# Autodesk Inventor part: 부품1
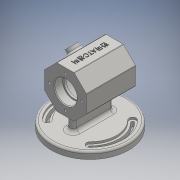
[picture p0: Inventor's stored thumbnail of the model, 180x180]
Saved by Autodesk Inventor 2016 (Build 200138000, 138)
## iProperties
Created: 2017-06
Part Number: 부품1
Material: 일반
Document SubType Name: Modeling
Designer: USER
Density: 1 g/cm^3
Appearance: 기본값
Author: USER
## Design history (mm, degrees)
sketch "스케치1"
  geometry: C1 r 55 at (0, 0); 1 further point
  constraints: 1 centre point, 1 coincident
  dimensions: "d0" = 110 diameter of C1
extrude "돌출1" new body sketch "스케치1" distance "d1" = 10; taper "d2" = 0 deg
sketch "스케치2"
  geometry: L1 (-55, 0)-(55, 0) reference; L2 (0, 62)-(0, 94.472); L3 (0, 62)-(-12.426, 92); L4 (0, 62)-(12.426, 92); L5 (12.426, 92)-(-12.426, 92); L6 (0, 62)-(-30, 74.426); L7 (0, 62)-(-30, 49.574); L8 (0, 62)-(-12.426, 32); L9 (0, 62)-(12.426, 32); L10 (0, 62)-(30, 49.574); L11 (0, 62)-(30, 74.426); L12 (-12.426, 92)-(-30, 74.426); L13 (-30, 49.574)-(-30, 74.426); L14 (-30, 49.574)-(-12.426, 32); L15 (-12.426, 32)-(12.426, 32); L16 (12.426, 32)-(30, 49.574); L17 (30, 49.574)-(30, 74.426); L18 (30, 74.426)-(12.426, 92); 3 further points
  constraints: 34 end point, 2 perpendicular, 2 vertical alignment, 1 coincident, 1 midpoint, 1 point on line, 1 vertical, 12 other
  dimensions: "d4" = 62 distance from line of point (0, 62) L1; "d10" = 22.5 deg angle of L2 L3; "d11" = 22.5 deg angle of L2 L4; "d12" = 92 distance from line of L4.end L1; "d13" = 45 deg angle of L3 L6; "d14" = 45 deg angle of L7 L6; "d15" = 45 deg angle of L7 L8; "d16" = 45 deg angle of L8 L9; "d17" = 45 deg angle of L10 L9; "d18" = 45 deg angle of L11 L10
extrude "돌출2" join sketch "스케치2" stored distance "d19" = 70; taper "d20" = 0 deg
sketch "스케치3"
  geometry: L1 (0, -24)-(0, 24); L2 (-5, -24)-(-5, 24); L3 (5, 24)-(5, -24); A1 r 5 centre (0, -24) between (-5, -24) and (5, -24); A2 r 5 centre (0, 24) between (5, 24) and (-5, 24); 3 further points
  constraints: 8 end point, 4 point on circle, 4 tangent, 2 centre point, 2 midpoint, 1 coincident, 1 horizontal alignment, 1 parallel, 1 vertical
  dimensions: "d21" = 48 distance of L1.end L1.start; "d22" = 5 radius of A1
extrude "돌출3" join sketch "스케치3" stored distance "d23" = 70; taper "d24" = 0 deg
sketch "스케치4"
  geometry: L1 (12.426, 92)-(-12.426, 92) reference; L2 (-12.426, 92)-(-30, 74.426) reference; L3 (-30, 74.426)-(-30, 49.574) reference; L4 (-30, 49.574)-(-12.426, 32) reference; L5 (-12.426, 32)-(12.426, 32) reference; L6 (12.426, 32)-(30, 49.574) reference; L7 (30, 49.574)-(30, 74.426) reference; L8 (30, 74.426)-(12.426, 92) reference; L9 (-55, 0)-(55, 0) reference; C1 r 16 at (0, 62); 2 further points
  constraints: 1 centre point, 1 midpoint, 1 vertical alignment
  dimensions: "d25" = 32 diameter of C1; "d26" = 62 distance from line of C1.centre L9
extrude "돌출4" cut sketch "스케치4" distance "d27" = 12; taper "d28" = 0 deg
sketch "스케치5"
  geometry: C1 r 16 at (0, 0) reference; C2 r 14 at (0, 0); 1 further point
  constraints: 1 centre point, 1 coincident
  dimensions: "d29" = 28 diameter of C2
extrude "돌출5" cut sketch "스케치5" distance "d30" = 3; taper "d31" = 0 deg
node "작업 평면1"
sketch "스케치6"
  geometry: L1 (12.426, 92)-(-12.426, 92) reference; L2 (-12.426, 92)-(-30, 74.426) reference; L3 (-30, 74.426)-(-30, 49.574) reference; L4 (-30, 49.574)-(-12.426, 32) reference; L5 (-12.426, 32)-(12.426, 32) reference; L6 (12.426, 32)-(30, 49.574) reference; L7 (30, 49.574)-(30, 74.426) reference; L8 (30, 74.426)-(12.426, 92) reference; C1 r 16 at (0, 62) reference; C2 r 25 at (0, 62); 1 further point
  constraints: 1 centre point, 1 coincident
  dimensions: "d32" = 50 diameter of C2
extrude "돌출6" cut sketch "스케치6" stored distance "d33" = 40; taper "d34" = 0 deg
sketch "스케치8"
  geometry: L1 (0, 0)-(-30.406, -30.406); L2 (0, 0)-(-30.406, 30.406); L3 (0, 0)-(-63.999, 0); A1 r 43 centre (0, 0) between (-30.406, 30.406) and (-30.406, -30.406); A2 r 48 centre (0, 0) between (-33.941, 33.941) and (-33.941, -33.941); A3 r 38 centre (0, 0) between (-26.87, 26.87) and (-26.87, -26.87); A4 r 5 centre (-30.406, 30.406) between (-26.87, 26.87) and (-33.941, 33.941); A5 r 5 centre (-30.406, -30.406) between (-33.941, -33.941) and (-26.87, -26.87); 2 further points
  constraints: 11 point on circle, 6 end point, 5 centre point, 4 tangent, 1 coincident, 1 horizontal, 1 horizontal alignment
  dimensions: "d35" = 38 radius of A3; "d36" = 48 radius of A2; "d37" = 90 deg angle of L2 L1
extrude "돌출7" cut sketch "스케치8" distance "d38" = 3; taper "d39" = 0 deg
sketch "스케치9"
  geometry: A1 r 48 centre (0, 0) between (-33.941, 33.941) and (-33.941, -33.941) reference; A2 r 5 centre (-30.406, -30.406) between (-33.941, -33.941) and (-26.87, -26.87) reference; A3 r 38 centre (0, 0) between (-26.87, 26.87) and (-26.87, -26.87) reference; A4 r 5 centre (-30.406, 30.406) between (-26.87, 26.87) and (-33.941, 33.941) reference; A5 r 45 centre (0, 0) between (-31.82, 31.82) and (-31.82, -31.82); A6 r 2 centre (-30.406, 30.406) between (-28.991, 28.991) and (-31.82, 31.82); A7 r 41 centre (0, 0) between (-28.991, 28.991) and (-28.991, -28.991); A8 r 2 centre (-30.406, -30.406) between (-31.82, -31.82) and (-28.991, -28.991); 1 further point
  constraints: 8 point on circle, 4 centre point, 3 other
  dimensions: "d40" = 3 radial gap between concentric circles of A1 A5
extrude "돌출8" cut sketch "스케치9" stored distance "d41" = 3; taper "d42" = 0 deg
node "작업 평면2"
chamfer "모따기1" distance "d43" = 1; stored, may be unused: second distance "d44" = 2, angle "d45" = 45 deg
fillet "모깎기1" dims "d46" = 3
fillet "모깎기2" dims "d47" = 0.3
sketch "스케치10" dims "d48" = 46
  geometry: C1 r 17 at (0, 62) reference; 3 further points
  constraints: 2 vertical alignment, 1 coincident, 2 other
hole "구멍1" sketch "스케치10" at (0, 85) diameter "d49" = 3.242; stored, may be unused: countersink angle "d53" = 90 deg, drill point angle "d55" = 118 deg; dims "d50" = 8, "d51" = 4, "d52" = 2, "d54" = 10
sketch "스케치11"
  geometry: L1 (0, 62)-(0, 102.776); L2 (0, 62)-(-29.041, 91.041); C1 r 25 at (0, 62) reference; 1 further point
  constraints: 4 end point, 1 vertical
  dimensions: "d59" = 45 deg angle of L1 L2
node "작업 평면4"
sketch "스케치16"
  geometry: L1 (-24.853, 70)-(0, 70) reference; C1 r 8 at (-12.426, 35); 2 further points
  constraints: 1 centre point, 1 horizontal alignment, 1 midpoint, 1 vertical alignment
  dimensions: "d67" = 16 diameter of C1
extrude "돌출11" join sketch "스케치16" distance "d68" = 7; taper "d69" = 0 deg
sketch "스케치17"
  geometry: C1 r 8 at (0, 0) reference; C2 r 4 at (0, 0); 1 further point
  constraints: 1 centre point, 1 coincident
  dimensions: "d70" = 8 diameter of C2
extrude "돌출12" cut sketch "스케치17" stored distance "d71" = 7; taper "d72" = 0 deg
fillet "모깎기3" dims "d73" = 3
fillet "모깎기4" dims "d74" = 1
fillet "모깎기5" dims "d75" = 3
fillet "모깎기6" dims "d76" = 5
sketch "스케치20"
  geometry: L1 (0, 0)-(24.024, 0) reference; 2 further points
  constraints: 1 coincident, 1 other
feature "엠보싱1" sketch "스케치20" dims "d78" = 0.5, "d79" = 0
node "작업 평면5"
node "솔리드1"
mirror "대칭1"
mirror "대칭2"
pattern_circular "원형 패턴1" dims angle "d57" = 360 deg
mirror "대칭3"
node "투영된 루프1"
node "투영된 루프2"
node "투영된 루프3"
node "투영된 루프4"
node "투영된 루프6"
other parameters: "d66" = 7
